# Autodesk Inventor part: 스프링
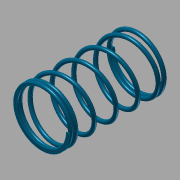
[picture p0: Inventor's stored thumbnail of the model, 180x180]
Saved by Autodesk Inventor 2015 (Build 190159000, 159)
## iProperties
Created: 2019-02
Part Number: 스프링
Material: 강철
Document SubType Name: Modeling
Designer: mduedu
Density: 2.18 g/cm^3
Appearance: 하늘색 짙음
CustomPartVersion: 1
Author: mduedu
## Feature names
1. Main Coil Feature(R)
2. Coil  Start Transition 2(R)
3. Coil  Start Transition 3(R)
4. Coil  Start Transition 4(R)
5. Plain Ends Cut  2(R) [Extrusion]
6. Main Coil Feature(L)
7. Cut Plain Ends Cut 1(L) [Extrusion]
8. Cut Plain Ends Cut 2(L) [Extrusion]
## Parameters: d0 = 0.25 mm, da_d = 1 mm, da_D2 = 13 mm, da_ti = 5.79943 mm, da_nz1 = 15 mm, spiral_Angle = 1.31102 mm, d2 = 5.79943 mm, d4 = 32.5 mm, d5 = 0, d6 = 90 deg, d7 = 90 deg, d8 = 0, d9 = 0, d12 = 3.09988 mm, d13 = -4.05199 mm, d14 = 1 mm, d15 = 0, d16 = 4.59957 mm, d18 = 2.5 mm, d19 = 0, d20 = 90 deg, d21 = 90 deg, d22 = 0, d23 = 0, d24 = 3.39971 mm, d26 = 2.5 mm, d27 = 0, d28 = 90 deg, d29 = 90 deg, d30 = 0, d31 = 0, d32 = 2.19986 mm, d34 = 2.5 mm, d35 = 0, d36 = 90 deg, d37 = 90 deg, d38 = 0, d39 = 0, d40 = 1 mm, d42 = 2.5 mm, d43 = 0, d44 = 90 deg, d45 = 90 deg, d46 = 0, d47 = 0, d48 = 4.59957 mm, d50 = 1.875 mm, d51 = 0, d52 = 90 deg, d53 = 90 deg, d54 = 0, d55 = 0, d56 = 3.39971 mm, d58 = 1.875 mm, d59 = 0, d60 = 90 deg, d61 = 90 deg, d62 = 0, d63 = 0, d64 = 2.19986 mm, d66 = 1.875 mm, d67 = 0, d68 = 90 deg, d69 = 90 deg, d70 = 0, d71 = 0, d72 = 1 mm, d74 = 1.875 mm, d75 = 0, d76 = 90 deg, d77 = 90 deg, d78 = 0, d79 = 0, End_Pitch = 1.00866 mm, d82 = 15 mm, d83 = 0, d84 = 90 deg, d85 = 90 deg, d86 = 0, d87 = 0, d88 = 1.00866 mm, d91 = 0, d92 = 90 deg, d93 = 90 deg, d94 = 0, d95 = 0, d96 = 15 mm, d97 = 1.00866 mm, d98 = 0, d99 = 15 mm, d100 = 1.00866 mm, d101 = 0, d102 = 0, d103 = 0, d104 = 0, d105 = 0, d106 = 0, d108 = 0, d112 = 0, d113 = 0, d114 = 0, const_zero = 0, Not_rightdir = 0, d121 = 0.26078 mm, d131 = 0, d132 = 0, d133 = 0, d134 = 0, d135 = 0.25 mm, d137 = 5.79943 mm, d139 = 32.5 mm, d140 = 0, d141 = 90 deg, d142 = 90 deg, d143 = 0, d144 = 0, d145 = 3.09988 mm, d146 = -4.05199 mm, d147 = 0.26078 mm, d148 = 0.00862 mm, d149 = 1 mm, d150 = 0, d151 = 0, d152 = 4.59957 mm, d154 = 2.5 mm, d155 = 0, d156 = 90 deg, d157 = 90 deg, d158 = 0, d159 = 0, d160 = 3.39971 mm, d162 = 2.5 mm, d163 = 0, d164 = 90 deg, d165 = 90 deg, d166 = 0, d167 = 0, d168 = 2.19986 mm, d170 = 2.5 mm, d171 = 0, d172 = 90 deg, d173 = 90 deg, d174 = 0, d175 = 0, d176 = 1 mm, d178 = 2.5 mm, d179 = 0, d180 = 90 deg, d181 = 90 deg, d182 = 0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
